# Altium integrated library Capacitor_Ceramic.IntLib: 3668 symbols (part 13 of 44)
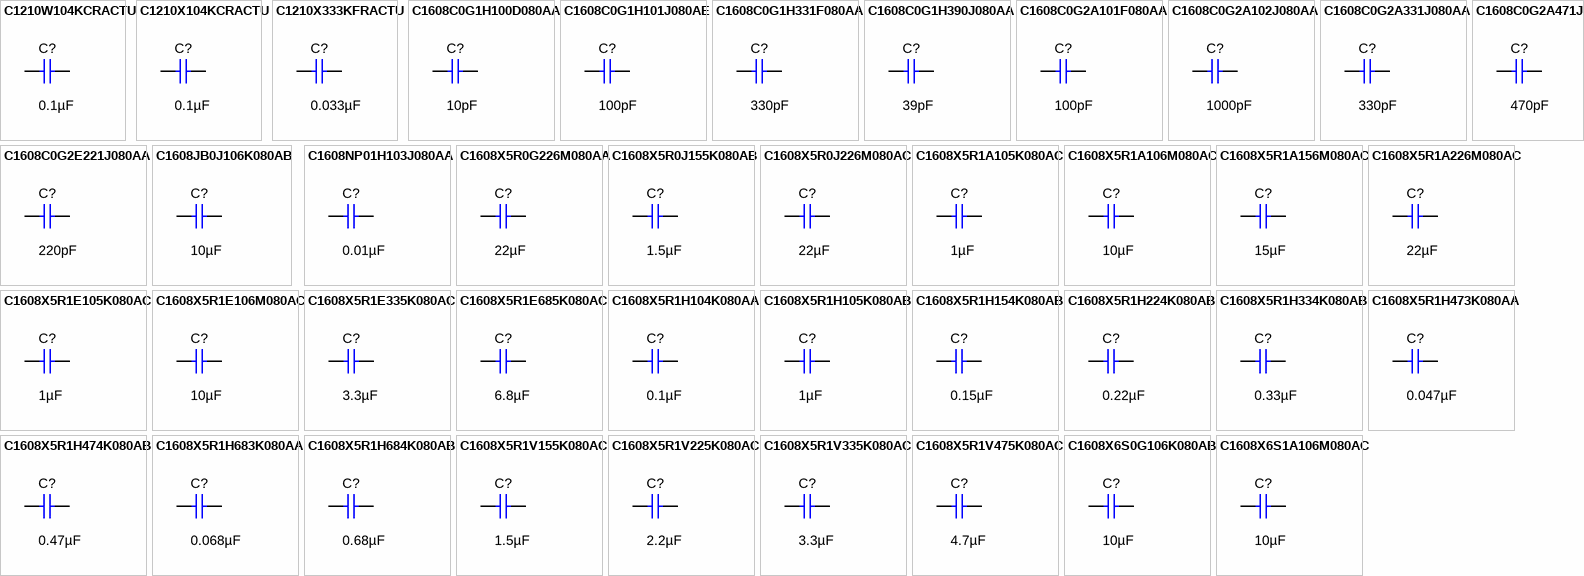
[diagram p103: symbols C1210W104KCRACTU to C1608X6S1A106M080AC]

## C1210X333KFRACTU
designator C?  ValueDisplayed: 0.033µF  (hidden comment: C1210X333KFRACTU)
CAP, CERM, 0.033 µF, 1500 V,+/- 10%, X7R, 1210; Manufacturer: Kemet; Polarized: N; CompType: Capacitor; Value: 0.033uF; U/M: EA; Cap_F: 0.000000033; Tolerance_%: 10; VDC_V: 1500; Value2: 1500V; TaMin_C: -55; TaMax_C: 125; Cap_Case: 1210; SizeArea_mm2: 8; SizeAreaWB_mm2: 14.7; SizeX_mm: 3.2; SizeY_mm: 2.5; SizeZ_mm: 2.8; AEC Category: Q200
signal-integrity model Cap
simulation model Cap
footprint 1210_280
pins: 1, 2

## C1608C0G1H100D080AA
designator C?  ValueDisplayed: 10pF  (hidden comment: C1608C0G1H100D080AA)
CAP, CERM, 10 pF, 50 V,+/- 5%, C0G/NP0, 0603; Manufacturer: TDK; Polarized: N; CompType: Capacitor; Value: 10pF; U/M: EA; Cap_F: 0.00000000001; Tolerance_%: 5; ESR_ohm: 0.3492; Value1: 0.3492 ohm; VDC_V: 50; Value2: 50V; TaMin_C: -55; TaMax_C: 125; Cap_Case: 0603; SizeArea_mm2: 1.28; SizeAreaWB_mm2: 4.68; SizeX_mm: 1.6; SizeY_mm: 0.8; SizeZ_mm: 1; AEC Category: Q200; Green_Lifecycle: NRND; Green_REACh: Passed
signal-integrity model Cap
simulation model Cap
footprint 0603
footprint 0603M
footprint 0603L
footprint 0603_HV
footprint 0603S
pins: 1, 2

## C1608C0G1H101J080AE
designator C?  ValueDisplayed: 100pF  (hidden comment: C1608C0G1H101J080AE)
CAP, CERM, 100 pF, 50 V,+/- 5%, C0G/NP0, 0603; Manufacturer: TDK; Polarized: N; CompType: Capacitor; Value: 100pF; U/M: EA; Cap_F: 0.0000000001; Tolerance_%: 5; VDC_V: 50; Value2: 50V; TaMin_C: -55; TaMax_C: 125; Cap_Case: 0603; SizeArea_mm2: 1.28; SizeAreaWB_mm2: 4.68; SizeX_mm: 1.6; SizeY_mm: 0.8; SizeZ_mm: 1; AEC Category: Q200; Green_Lifecycle: Active; Green_REACh: Passed
signal-integrity model Cap
simulation model Cap
footprint 0603
footprint 0603M
footprint 0603L
footprint 0603_HV
footprint 0603S
pins: 1, 2

## C1608C0G1H331F080AA
designator C?  ValueDisplayed: 330pF  (hidden comment: C1608C0G1H331F080AA)
CAP, CERM, 330 pF, 50 V,+/- 1%, C0G/NP0, 0603; Manufacturer: TDK; Polarized: N; CompType: Capacitor; Value: 330pF; U/M: EA; Cap_F: 0.00000000033; Tolerance_%: 1; VDC_V: 50; Value2: 50V; TaMin_C: -55; TaMax_C: 125; Cap_Case: 0603; SizeArea_mm2: 1.28; SizeAreaWB_mm2: 4.68; SizeX_mm: 1.6; SizeY_mm: 0.8; AEC Category: Q200; Green_Lifecycle: NRND; Green_REACh: Passed
signal-integrity model Cap
simulation model Cap
footprint 0603
footprint 0603M
footprint 0603L
footprint 0603_HV
footprint 0603S
pins: 1, 2

## C1608C0G1H390J080AA
designator C?  ValueDisplayed: 39pF  (hidden comment: C1608C0G1H390J080AA)
CAP, CERM, 39 pF, 50 V,+/- 5%, C0G/NP0, 0603; Manufacturer: TDK; Polarized: N; CompType: Capacitor; Value: 39pF; U/M: EA; Cap_F: 0.000000000039; Tolerance_%: 5; ESR_ohm: 0.2534; Value1: 0.2534 ohm; VDC_V: 50; Value2: 50V; TaMin_C: -55; TaMax_C: 125; Cap_Case: 0603; SizeArea_mm2: 1.28; SizeAreaWB_mm2: 4.68; SizeX_mm: 1.6; SizeY_mm: 0.8; SizeZ_mm: 1; AEC Category: Q200; Green_Lifecycle: NRND; Green_REACh: Passed
signal-integrity model Cap
simulation model Cap
footprint 0603
footprint 0603M
footprint 0603L
footprint 0603_HV
footprint 0603S
pins: 1, 2

## C1608C0G2A101F080AA
designator C?  ValueDisplayed: 100pF  (hidden comment: C1608C0G2A101F080AA)
CAP, CERM, 100 pF, 100 V,+/- 1%, C0G/NP0, 0603; Manufacturer: TDK; Polarized: N; CompType: Capacitor; Value: 100pF; U/M: EA; Cap_F: 0.0000000001; Tolerance_%: 1; VDC_V: 100; Value2: 100V; TaMin_C: -55; TaMax_C: 125; Cap_Case: 0603; SizeArea_mm2: 1.28; SizeAreaWB_mm2: 4.68; SizeX_mm: 1.6; SizeY_mm: 0.8; AEC Category: Q200; Green_Lifecycle: NRND; Green_REACh: Passed
signal-integrity model Cap
simulation model Cap
footprint 0603
footprint 0603M
footprint 0603L
footprint 0603_HV
footprint 0603S
pins: 1, 2

## C1608C0G2A102J080AA
designator C?  ValueDisplayed: 1000pF  (hidden comment: C1608C0G2A102J080AA)
CAP, CERM, 1000 pF, 100 V,+/- 5%, C0G/NP0, 0603; Manufacturer: TDK; Polarized: N; CompType: Capacitor; Value: 1000pF; U/M: EA; Cap_F: 0.000000001; Tolerance_%: 5; ESR_ohm: 0.0589; Value1: 0.0589 ohm; VDC_V: 100; Value2: 100V; TaMin_C: -55; TaMax_C: 125; Cap_Case: 0603; SizeArea_mm2: 1.28; SizeAreaWB_mm2: 4.68; SizeX_mm: 1.6; SizeY_mm: 0.8; SizeZ_mm: 1; AEC Category: Q200; Green_Lifecycle: Active; Green_REACh: Passed
signal-integrity model Cap
simulation model Cap
footprint 0603
footprint 0603M
footprint 0603L
footprint 0603_HV
footprint 0603S
pins: 1, 2

## C1608C0G2A331J080AA
designator C?  ValueDisplayed: 330pF  (hidden comment: C1608C0G2A331J080AA)
CAP, CERM, 330 pF, 100 V,+/- 5%, C0G/NP0, 0603; Manufacturer: TDK; Polarized: N; CompType: Capacitor; Value: 330pF; U/M: EA; Cap_F: 0.00000000033; Tolerance_%: 5; ESR_ohm: 0.1269; Value1: 0.1269 ohm; VDC_V: 100; Value2: 100V; TaMin_C: -55; TaMax_C: 125; Cap_Case: 0603; SizeArea_mm2: 1.28; SizeAreaWB_mm2: 4.68; SizeX_mm: 1.6; SizeY_mm: 0.8; SizeZ_mm: 1; AEC Category: Q200; Green_Lifecycle: Active; Green_REACh: Passed
signal-integrity model Cap
simulation model Cap
footprint 0603
footprint 0603M
footprint 0603L
footprint 0603_HV
footprint 0603S
pins: 1, 2

## C1608C0G2A471J
designator C?  ValueDisplayed: 470pF  (hidden comment: C1608C0G2A471J)
CAP, CERM, 470 pF, 100 V,+/- 5%, C0G/NP0, 0603; Manufacturer: TDK; Polarized: N; CompType: Capacitor; Value: 470pF; U/M: EA; Cap_F: 0.00000000047; Tolerance_%: 5; ESR_ohm: 0.0714; Value1: 0.0714 ohm; VDC_V: 100; Value2: 100V; TaMin_C: -55; TaMax_C: 125; Cap_Case: 0603; SizeArea_mm2: 1.28; SizeAreaWB_mm2: 4.68; SizeX_mm: 1.6; SizeY_mm: 0.8; SizeZ_mm: 1; AEC Category: Q200; Green_Lifecycle: Not Set; Green_REACh: Incomplete
signal-integrity model Cap
simulation model Cap
footprint 0603
footprint 0603M
footprint 0603L
footprint 0603_HV
footprint 0603S
pins: 1, 2

## C1608C0G2E221J080AA
designator C?  ValueDisplayed: 220pF  (hidden comment: C1608C0G2E221J080AA)
CAP, CERM, 220 pF, 250 V,+/- 5%, C0G/NP0, 0603; Manufacturer: TDK; Polarized: N; CompType: Capacitor; Value: 220pF; U/M: EA; Cap_F: 0.00000000022; Tolerance_%: 5; VDC_V: 250; Value2: 250V; TaMin_C: -55; TaMax_C: 125; Cap_Case: 0603; SizeArea_mm2: 1.28; SizeAreaWB_mm2: 4.68; SizeX_mm: 1.6; SizeY_mm: 0.8; SizeZ_mm: 1; AEC Category: Q200
signal-integrity model Cap
simulation model Cap
footprint 0603
footprint 0603M
footprint 0603L
footprint 0603_HV
footprint 0603S
pins: 1, 2

## C1608JB0J106K080AB
designator C?  ValueDisplayed: 10µF  (hidden comment: C1608JB0J106K080AB)
CAP, CERM, 10 µF, 6.3 V,+/- 10%, JB, 0603; Manufacturer: TDK; Polarized: N; CompType: Capacitor; Value: 10uF; U/M: EA; Cap_F: 0.00001; Tolerance_%: 10; VDC_V: 6.3; Value2: 6.3V; TaMin_C: -25; TaMax_C: 85; Cap_Case: 0603; SizeArea_mm2: 1.28; SizeAreaWB_mm2: 4.68; SizeX_mm: 1.6; SizeY_mm: 0.8; SizeZ_mm: 1; AEC Category: Q200
signal-integrity model Cap
simulation model Cap
footprint 0603
footprint 0603M
footprint 0603L
footprint 0603_HV
footprint 0603S
pins: 1, 2

## C1608NP01H103J080AA
designator C?  ValueDisplayed: 0.01µF  (hidden comment: C1608NP01H103J080AA)
CAP, CERM, 0.01 µF, 50 V,+/- 5%, C0G/NP0, 0603; Manufacturer: TDK; Polarized: N; CompType: Capacitor; Value: 0.01uF; U/M: EA; Cap_F: 0.00000001; Tolerance_%: 5; VDC_V: 50; Value2: 50V; TaMin_C: -55; TaMax_C: 150; Cap_Case: 0603; SizeArea_mm2: 1.28; SizeAreaWB_mm2: 4.68; SizeX_mm: 1.6; SizeY_mm: 0.8; SizeZ_mm: 1; AEC Category: Q200; Green_Lifecycle: Not Set; Green_REACh: Incomplete
signal-integrity model Cap
simulation model Cap
footprint 0603
footprint 0603M
footprint 0603L
footprint 0603_HV
footprint 0603S
pins: 1, 2

## C1608X5R0G226M080AA
designator C?  ValueDisplayed: 22µF  (hidden comment: C1608X5R0G226M080AA)
CAP, CERM, 22 µF, 4 V,+/- 20%, X5R, 0603; Manufacturer: TDK; Polarized: N; CompType: Capacitor; Value: 22uF; U/M: EA; Cap_F: 0.000022; Tolerance_%: 20; VDC_V: 4; Value2: 4V; TaMin_C: -55; TaMax_C: 85; Cap_Case: 0603; SizeArea_mm2: 1.28; SizeAreaWB_mm2: 4.68; SizeX_mm: 1.6; SizeY_mm: 0.8; SizeZ_mm: 1; AEC Category: Q200; Green_Lifecycle: Active; Green_REACh: Passed
signal-integrity model Cap
simulation model Cap
footprint 0603
footprint 0603M
footprint 0603L
footprint 0603_HV
footprint 0603S
pins: 1, 2

## C1608X5R0J155K080AB
designator C?  ValueDisplayed: 1.5µF  (hidden comment: C1608X5R0J155K080AB)
CAP, CERM, 1.5 µF, 6.3 V,+/- 10%, X5R, 0603; Manufacturer: TDK; Polarized: N; CompType: Capacitor; Value: 1.5uF; U/M: EA; Cap_F: 0.0000015; Tolerance_%: 10; VDC_V: 6.3; Value2: 6.3V; TaMin_C: -55; TaMax_C: 85; Cap_Case: 0603; SizeArea_mm2: 1.28; SizeAreaWB_mm2: 4.68; SizeX_mm: 1.6; SizeY_mm: 0.8; SizeZ_mm: 1; AEC Category: Q200
signal-integrity model Cap
simulation model Cap
footprint 0603
footprint 0603M
footprint 0603L
footprint 0603_HV
footprint 0603S
pins: 1, 2

## C1608X5R0J226M080AC
designator C?  ValueDisplayed: 22µF  (hidden comment: C1608X5R0J226M080AC)
CAP, CERM, 22 µF, 6.3 V,+/- 20%, X5R, 0603; Manufacturer: TDK; Polarized: N; CompType: Capacitor; Value: 22uF; U/M: EA; Cap_F: 0.000022; Tolerance_%: 20; VDC_V: 6.3; Value2: 6.3V; TaMin_C: -55; TaMax_C: 85; Cap_Case: 0603; SizeArea_mm2: 1.28; SizeAreaWB_mm2: 4.68; SizeX_mm: 1.6; SizeY_mm: 0.8; SizeZ_mm: 1; AEC Category: Q200; Green_Lifecycle: Active; Green_REACh: Passed
signal-integrity model Cap
simulation model Cap
footprint 0603
footprint 0603M
footprint 0603L
footprint 0603_HV
footprint 0603S
pins: 1, 2

## C1608X5R1A105K080AC
designator C?  ValueDisplayed: 1µF  (hidden comment: C1608X5R1A105K080AC)
CAP, CERM, 1 µF, 10 V,+/- 10%, X5R, 0603; Manufacturer: TDK; Polarized: N; CompType: Capacitor; Value: 1uF; U/M: EA; Cap_F: 0.000001; Tolerance_%: 10; Value2: 10V; TaMin_C: -55; TaMax_C: 85; Cap_Case: 0603; SizeArea_mm2: 1.28; SizeAreaWB_mm2: 4.68; SizeX_mm: 1.6; SizeY_mm: 0.8; SizeZ_mm: 1; AEC Category: Q200; Green_Lifecycle: NRND; Green_REACh: Passed
signal-integrity model Cap
simulation model Cap
footprint 0603
footprint 0603M
footprint 0603L
footprint 0603_HV
footprint 0603S
pins: 1, 2

## C1608X5R1A106M080AC
designator C?  ValueDisplayed: 10µF  (hidden comment: C1608X5R1A106M080AC)
CAP, CERM, 10 µF, 10 V,+/- 20%, X5R, 0603; Manufacturer: TDK; Polarized: N; CompType: Capacitor; Value: 10uF; U/M: EA; Cap_F: 0.00001; Tolerance_%: 20; ESR_ohm: 0.0078; Value1: 0.0078 ohm; VDC_V: 10; Value2: 10V; IRMS_A: 1.85; TaMin_C: -55; TaMax_C: 85; Cap_Case: 0603; SizeArea_mm2: 1.28; SizeAreaWB_mm2: 4.68; SizeX_mm: 1.6; SizeY_mm: 0.8; SizeZ_mm: 1; AEC Category: Q200; Green_Lifecycle: Active; Green_REACh: Passed
signal-integrity model Cap
simulation model Cap
footprint 0603
footprint 0603M
footprint 0603L
footprint 0603_HV
footprint 0603S
pins: 1, 2

## C1608X5R1A156M080AC
designator C?  ValueDisplayed: 15µF  (hidden comment: C1608X5R1A156M080AC)
CAP, CERM, 15 µF, 10 V,+/- 20%, X5R, 0603; Manufacturer: TDK; Polarized: N; CompType: Capacitor; Value: 15uF; U/M: EA; Cap_F: 0.000015; Tolerance_%: 20; ESR_ohm: 0.006531; Value1: 0.006531 ohm; VDC_V: 10; Value2: 10V; IRMS_A: 2.03438; TaMin_C: -55; TaMax_C: 85; Cap_Case: 0603; SizeArea_mm2: 1.28; SizeAreaWB_mm2: 4.68; SizeX_mm: 1.6; SizeY_mm: 0.8; SizeZ_mm: 1; AEC Category: Q200
signal-integrity model Cap
simulation model Cap
footprint 0603
footprint 0603M
footprint 0603L
footprint 0603_HV
footprint 0603S
pins: 1, 2

## C1608X5R1A226M080AC
designator C?  ValueDisplayed: 22µF  (hidden comment: C1608X5R1A226M080AC)
CAP, CERM, 22 µF, 10 V,+/- 20%, X5R, 0603; Manufacturer: TDK; Polarized: N; CompType: Capacitor; Value: 22uF; U/M: EA; Cap_F: 0.000022; Tolerance_%: 20; ESR_ohm: 0.00371; Value1: 0.00371 ohm; VDC_V: 10; Value2: 10V; IRMS_A: 2.69936; TaMin_C: -55; TaMax_C: 85; Cap_Case: 0603; SizeArea_mm2: 1.28; SizeAreaWB_mm2: 4.68; SizeX_mm: 1.6; SizeY_mm: 0.8; SizeZ_mm: 1; AEC Category: Q200; Green_Lifecycle: Active; Green_REACh: Passed
signal-integrity model Cap
simulation model Cap
footprint 0603
footprint 0603M
footprint 0603L
footprint 0603_HV
footprint 0603S
pins: 1, 2

## C1608X5R1E105K080AC
designator C?  ValueDisplayed: 1µF  (hidden comment: C1608X5R1E105K080AC)
CAP, CERM, 1 µF, 25 V,+/- 10%, X5R, 0603; Manufacturer: TDK; Polarized: N; CompType: Capacitor; Value: 1uF; U/M: EA; Cap_F: 0.000001; Tolerance_%: 10; VDC_V: 25; Value2: 25V; TaMin_C: -55; TaMax_C: 85; Cap_Case: 0603; SizeArea_mm2: 1.28; SizeAreaWB_mm2: 4.68; SizeX_mm: 1.6; SizeY_mm: 0.8; SizeZ_mm: 1; AEC Category: Q200; Green_Lifecycle: Active; Green_REACh: Passed
signal-integrity model Cap
simulation model Cap
footprint 0603
footprint 0603M
footprint 0603L
footprint 0603_HV
footprint 0603S
pins: 1, 2

## C1608X5R1E106M080AC
designator C?  ValueDisplayed: 10µF  (hidden comment: C1608X5R1E106M080AC)
CAP, CERM, 10 µF, 25 V,+/- 20%, X5R, 0603; Manufacturer: TDK; Polarized: N; CompType: Capacitor; Value: 10uF; U/M: EA; Cap_F: 0.00001; Tolerance_%: 20; ESR_ohm: 0.004639; Value1: 0.004639 ohm; VDC_V: 25; Value2: 25V; IRMS_A: 2.41407; TaMin_C: -55; TaMax_C: 85; Cap_Case: 0603; SizeArea_mm2: 1.28; SizeAreaWB_mm2: 4.68; SizeX_mm: 1.6; SizeY_mm: 0.8; SizeZ_mm: 1; AEC Category: Q200; Green_Lifecycle: Active; Green_REACh: Passed
signal-integrity model Cap
simulation model Cap
footprint 0603
footprint 0603M
footprint 0603L
footprint 0603_HV
footprint 0603S
pins: 1, 2

## C1608X5R1E335K080AC
designator C?  ValueDisplayed: 3.3µF  (hidden comment: C1608X5R1E335K080AC)
CAP, CERM, 3.3 µF, 25 V,+/- 10%, X5R, 0603; Manufacturer: TDK; Polarized: N; CompType: Capacitor; Value: 3.3uF; U/M: EA; Cap_F: 0.0000033; Tolerance_%: 10; VDC_V: 25; Value2: 25V; TaMin_C: -55; TaMax_C: 85; Cap_Case: 0603; SizeArea_mm2: 1.28; SizeAreaWB_mm2: 4.68; SizeX_mm: 1.6; SizeY_mm: 0.8; SizeZ_mm: 1; AEC Category: Q200; Green_Lifecycle: Active; Green_REACh: Passed
signal-integrity model Cap
simulation model Cap
footprint 0603
footprint 0603M
footprint 0603L
footprint 0603_HV
footprint 0603S
pins: 1, 2

## C1608X5R1E685K080AC
designator C?  ValueDisplayed: 6.8µF  (hidden comment: C1608X5R1E685K080AC)
CAP, CERM, 6.8 µF, 25 V,+/- 10%, X5R, 0603; Manufacturer: TDK; Polarized: N; CompType: Capacitor; Value: 6.8uF; U/M: EA; Cap_F: 0.0000068; Tolerance_%: 10; ESR_ohm: 0.004211; Value1: 0.004211 ohm; VDC_V: 25; Value2: 25V; IRMS_A: 2.534067; TaMin_C: -55; TaMax_C: 85; Cap_Case: 0603; SizeArea_mm2: 1.28; SizeAreaWB_mm2: 4.68; SizeX_mm: 1.6; SizeY_mm: 0.8; SizeZ_mm: 1; AEC Category: Q200
signal-integrity model Cap
simulation model Cap
footprint 0603
footprint 0603M
footprint 0603L
footprint 0603_HV
footprint 0603S
pins: 1, 2

## C1608X5R1H104K080AA
designator C?  ValueDisplayed: 0.1µF  (hidden comment: C1608X5R1H104K080AA)
CAP, CERM, 0.1 µF, 50 V,+/- 10%, X5R, 0603; Manufacturer: TDK; Polarized: N; CompType: Capacitor; Value: 0.1uF; U/M: EA; Cap_F: 0.0000001; Tolerance_%: 10; ESR_ohm: 0.0296; Value1: 0.0296 ohm; VDC_V: 50; Value2: 50V; IRMS_A: 0.97199; TaMin_C: -55; TaMax_C: 85; Cap_Case: 0603; SizeArea_mm2: 1.28; SizeAreaWB_mm2: 4.68; SizeX_mm: 1.6; SizeY_mm: 0.8; SizeZ_mm: 1; AEC Category: Q200; Green_Lifecycle: NRND; Green_REACh: Passed
signal-integrity model Cap
simulation model Cap
footprint 0603
footprint 0603M
footprint 0603L
footprint 0603_HV
footprint 0603S
pins: 1, 2

## C1608X5R1H105K080AB
designator C?  ValueDisplayed: 1µF  (hidden comment: C1608X5R1H105K080AB)
CAP, CERM, 1 µF, 50 V,+/- 10%, X5R, 0603; Manufacturer: TDK; Polarized: N; CompType: Capacitor; Value: 1uF; U/M: EA; Cap_F: 0.000001; Tolerance_%: 10; ESR_ohm: 0.005522; Value1: 0.005522 ohm; VDC_V: 50; Value2: 50V; IRMS_A: 2.21617; TaMin_C: -55; TaMax_C: 85; Cap_Case: 0603; SizeArea_mm2: 1.28; SizeAreaWB_mm2: 4.68; SizeX_mm: 1.6; SizeY_mm: 0.8; SizeZ_mm: 1; AEC Category: Q200; Green_Lifecycle: Active; Green_REACh: Passed
signal-integrity model Cap
simulation model Cap
footprint 0603
footprint 0603M
footprint 0603L
footprint 0603_HV
footprint 0603S
pins: 1, 2

## C1608X5R1H154K080AB
designator C?  ValueDisplayed: 0.15µF  (hidden comment: C1608X5R1H154K080AB)
CAP, CERM, 0.15 µF, 50 V,+/- 10%, X5R, 0603; Manufacturer: TDK; Polarized: N; CompType: Capacitor; Value: 0.15uF; U/M: EA; Cap_F: 0.00000015; Tolerance_%: 10; ESR_ohm: 0.028863; Value1: 0.028863 ohm; VDC_V: 50; Value2: 50V; IRMS_A: 0.978809; TaMin_C: -55; TaMax_C: 85; Cap_Case: 0603; SizeArea_mm2: 1.28; SizeAreaWB_mm2: 4.68; SizeX_mm: 1.6; SizeY_mm: 0.8; SizeZ_mm: 1; AEC Category: Q200
signal-integrity model Cap
simulation model Cap
footprint 0603
footprint 0603M
footprint 0603L
footprint 0603_HV
footprint 0603S
pins: 1, 2

## C1608X5R1H224K080AB
designator C?  ValueDisplayed: 0.22µF  (hidden comment: C1608X5R1H224K080AB)
CAP, CERM, 0.22 µF, 50 V,+/- 10%, X5R, 0603; Manufacturer: TDK; Polarized: N; CompType: Capacitor; Value: 0.22uF; U/M: EA; Cap_F: 0.00000022; Tolerance_%: 10; ESR_ohm: 0.021699; Value1: 0.021699 ohm; VDC_V: 50; Value2: 50V; IRMS_A: 1.12496; TaMin_C: -55; TaMax_C: 85; Cap_Case: 0603; SizeArea_mm2: 1.28; SizeAreaWB_mm2: 4.68; SizeX_mm: 1.6; SizeY_mm: 0.8; SizeZ_mm: 1; AEC Category: Q200
signal-integrity model Cap
simulation model Cap
footprint 0603
footprint 0603M
footprint 0603L
footprint 0603_HV
footprint 0603S
pins: 1, 2

## C1608X5R1H334K080AB
designator C?  ValueDisplayed: 0.33µF  (hidden comment: C1608X5R1H334K080AB)
CAP, CERM, 0.33 µF, 50 V,+/- 10%, X5R, 0603; Manufacturer: TDK; Polarized: N; CompType: Capacitor; Value: 0.33uF; U/M: EA; Cap_F: 0.00000033; Tolerance_%: 10; ESR_ohm: 0.016574; Value1: 0.016574 ohm; VDC_V: 50; Value2: 50V; IRMS_A: 1.28367; TaMin_C: -55; TaMax_C: 85; Cap_Case: 0603; SizeArea_mm2: 1.28; SizeAreaWB_mm2: 4.68; SizeX_mm: 1.6; SizeY_mm: 0.8; SizeZ_mm: 1; AEC Category: Q200
signal-integrity model Cap
simulation model Cap
footprint 0603
footprint 0603M
footprint 0603L
footprint 0603_HV
footprint 0603S
pins: 1, 2

## C1608X5R1H473K080AA
designator C?  ValueDisplayed: 0.047µF  (hidden comment: C1608X5R1H473K080AA)
CAP, CERM, 0.047 µF, 50 V,+/- 10%, X5R, 0603; Manufacturer: TDK; Polarized: N; CompType: Capacitor; Value: 0.047uF; U/M: EA; Cap_F: 0.000000047; Tolerance_%: 10; ESR_ohm: 0.049007; Value1: 0.049007 ohm; VDC_V: 50; Value2: 50V; IRMS_A: 0.767528; TaMin_C: -55; TaMax_C: 85; Cap_Case: 0603; SizeArea_mm2: 1.28; SizeAreaWB_mm2: 4.68; SizeX_mm: 1.6; SizeY_mm: 0.8; SizeZ_mm: 1; AEC Category: Q200; Green_Lifecycle: NRND; Green_REACh: Passed
signal-integrity model Cap
simulation model Cap
footprint 0603
footprint 0603M
footprint 0603L
footprint 0603_HV
footprint 0603S
pins: 1, 2

## C1608X5R1H474K080AB
designator C?  ValueDisplayed: 0.47µF  (hidden comment: C1608X5R1H474K080AB)
CAP, CERM, 0.47 µF, 50 V,+/- 10%, X5R, 0603; Manufacturer: TDK; Polarized: N; CompType: Capacitor; Value: 0.47uF; U/M: EA; Cap_F: 0.00000047; Tolerance_%: 10; ESR_ohm: 0.010974; Value1: 0.010974 ohm; VDC_V: 50; Value2: 50V; IRMS_A: 1.57483; TaMin_C: -55; TaMax_C: 85; Cap_Case: 0603; SizeArea_mm2: 1.28; SizeAreaWB_mm2: 4.68; SizeX_mm: 1.6; SizeY_mm: 0.8; SizeZ_mm: 1; AEC Category: Q200
signal-integrity model Cap
simulation model Cap
footprint 0603
footprint 0603M
footprint 0603L
footprint 0603_HV
footprint 0603S
pins: 1, 2

## C1608X5R1H683K080AA
designator C?  ValueDisplayed: 0.068µF  (hidden comment: C1608X5R1H683K080AA)
CAP, CERM, 0.068 µF, 50 V,+/- 10%, X5R, 0603; Manufacturer: TDK; Polarized: N; CompType: Capacitor; Value: 0.068uF; U/M: EA; Cap_F: 0.000000068; Tolerance_%: 10; ESR_ohm: 0.035979; Value1: 0.035979 ohm; VDC_V: 50; Value2: 50V; IRMS_A: 0.886483; TaMin_C: -55; TaMax_C: 85; Cap_Case: 0603; SizeArea_mm2: 1.28; SizeAreaWB_mm2: 4.68; SizeX_mm: 1.6; SizeY_mm: 0.8; SizeZ_mm: 1; AEC Category: Q200; Green_Lifecycle: NRND; Green_REACh: Passed
signal-integrity model Cap
simulation model Cap
footprint 0603
footprint 0603M
footprint 0603L
footprint 0603_HV
footprint 0603S
pins: 1, 2

## C1608X5R1H684K080AB
designator C?  ValueDisplayed: 0.68µF  (hidden comment: C1608X5R1H684K080AB)
CAP, CERM, 0.68 µF, 50 V,+/- 10%, X5R, 0603; Manufacturer: TDK; Polarized: N; CompType: Capacitor; Value: 0.68uF; U/M: EA; Cap_F: 0.00000068; Tolerance_%: 10; ESR_ohm: 0.007125; Value1: 0.007125 ohm; VDC_V: 50; Value2: 50V; IRMS_A: 1.9522; TaMin_C: -55; TaMax_C: 85; Cap_Case: 0603; SizeArea_mm2: 1.28; SizeAreaWB_mm2: 4.68; SizeX_mm: 1.6; SizeY_mm: 0.8; SizeZ_mm: 1; AEC Category: Q200
signal-integrity model Cap
simulation model Cap
footprint 0603
footprint 0603M
footprint 0603L
footprint 0603_HV
footprint 0603S
pins: 1, 2

## C1608X5R1V155K080AC
designator C?  ValueDisplayed: 1.5µF  (hidden comment: C1608X5R1V155K080AC)
CAP, CERM, 1.5 µF, 35 V,+/- 10%, X5R, 0603; Manufacturer: TDK; Polarized: N; CompType: Capacitor; Value: 1.5uF; U/M: EA; Cap_F: 0.0000015; Tolerance_%: 10; ESR_ohm: 0.009039; Value1: 0.009039 ohm; VDC_V: 35; Value2: 35V; IRMS_A: 1.73141; TaMin_C: -55; TaMax_C: 85; Cap_Case: 0603; SizeArea_mm2: 1.28; SizeAreaWB_mm2: 4.68; SizeX_mm: 1.6; SizeY_mm: 0.8; SizeZ_mm: 1; AEC Category: Q200
signal-integrity model Cap
simulation model Cap
footprint 0603
footprint 0603M
footprint 0603L
footprint 0603_HV
footprint 0603S
pins: 1, 2

## C1608X5R1V225K080AC
designator C?  ValueDisplayed: 2.2µF  (hidden comment: C1608X5R1V225K080AC)
CAP, CERM, 2.2 µF, 35 V,+/- 10%, X5R, 0603; Manufacturer: TDK; Polarized: N; CompType: Capacitor; Value: 2.2uF; U/M: EA; Cap_F: 0.0000022; Tolerance_%: 10; ESR_ohm: 0.007674; Value1: 0.007674 ohm; VDC_V: 35; Value2: 35V; IRMS_A: 1.87823; TaMin_C: -55; TaMax_C: 85; Cap_Case: 0603; SizeArea_mm2: 1.28; SizeAreaWB_mm2: 4.68; SizeX_mm: 1.6; SizeY_mm: 0.8; SizeZ_mm: 1; AEC Category: Q200; Green_Lifecycle: Active; Green_REACh: Passed
signal-integrity model Cap
simulation model Cap
footprint 0603
footprint 0603M
footprint 0603L
footprint 0603_HV
footprint 0603S
pins: 1, 2

## C1608X5R1V335K080AC
designator C?  ValueDisplayed: 3.3µF  (hidden comment: C1608X5R1V335K080AC)
CAP, CERM, 3.3 µF, 35 V,+/- 10%, X5R, 0603; Manufacturer: TDK; Polarized: N; CompType: Capacitor; Value: 3.3uF; U/M: EA; Cap_F: 0.0000033; Tolerance_%: 10; ESR_ohm: 0.004796; Value1: 0.004796 ohm; VDC_V: 35; Value2: 35V; IRMS_A: 2.37519; TaMin_C: -55; TaMax_C: 85; Cap_Case: 0603; SizeArea_mm2: 1.28; SizeAreaWB_mm2: 4.68; SizeX_mm: 1.6; SizeY_mm: 0.8; SizeZ_mm: 1; AEC Category: Q200
signal-integrity model Cap
simulation model Cap
footprint 0603
footprint 0603M
footprint 0603L
footprint 0603_HV
footprint 0603S
pins: 1, 2

## C1608X5R1V475K080AC
designator C?  ValueDisplayed: 4.7µF  (hidden comment: C1608X5R1V475K080AC)
CAP, CERM, 4.7 µF, 35 V,+/- 10%, X5R, 0603; Manufacturer: TDK; Polarized: N; CompType: Capacitor; Value: 4.7uF; U/M: EA; Cap_F: 0.0000047; Tolerance_%: 10; ESR_ohm: 0.003728; Value1: 0.003728 ohm; VDC_V: 35; Value2: 35V; IRMS_A: 2.69359; TaMin_C: -55; TaMax_C: 85; Cap_Case: 0603; SizeArea_mm2: 1.28; SizeAreaWB_mm2: 4.68; SizeX_mm: 1.6; SizeY_mm: 0.8; SizeZ_mm: 1; AEC Category: Q200
signal-integrity model Cap
simulation model Cap
footprint 0603
footprint 0603M
footprint 0603L
footprint 0603_HV
footprint 0603S
pins: 1, 2

## C1608X6S0G106K080AB
designator C?  ValueDisplayed: 10µF  (hidden comment: C1608X6S0G106K080AB)
CAP, CERM, 10 µF, 4 V,+/- 10%, X6S, 0603; Manufacturer: TDK; Polarized: N; CompType: Capacitor; Value: 10uF; U/M: EA; Cap_F: 0.00001; Tolerance_%: 10; VDC_V: 4; Value2: 4V; TaMin_C: -55; TaMax_C: 105; Cap_Case: 0603; SizeArea_mm2: 1.28; SizeAreaWB_mm2: 4.68; SizeX_mm: 1.6; SizeY_mm: 0.8; SizeZ_mm: 1; AEC Category: Q200
signal-integrity model Cap
simulation model Cap
footprint 0603
footprint 0603M
footprint 0603L
footprint 0603_HV
footprint 0603S
pins: 1, 2

## C1608X6S1A106M080AC
designator C?  ValueDisplayed: 10µF  (hidden comment: C1608X6S1A106M080AC)
CAP, CERM, 10 µF, 10 V,+/- 10%, X6S, 0603; Manufacturer: TDK; Polarized: N; CompType: Capacitor; Value: 10uF; U/M: EA; Cap_F: 0.00001; Tolerance_%: 10; ESR_ohm: 0.004639; Value1: 0.004639 ohm; Value2: 10V; IRMS_A: 2.41407; TaMin_C: -55; TaMax_C: 105; Cap_Case: 0603; SizeArea_mm2: 1.28; SizeAreaWB_mm2: 4.68; SizeX_mm: 1.6; SizeY_mm: 0.8; SizeZ_mm: 1; AEC Category: Q200
signal-integrity model Cap
simulation model Cap
footprint 0603
footprint 0603M
footprint 0603L
footprint 0603_HV
footprint 0603S
pins: 1, 2

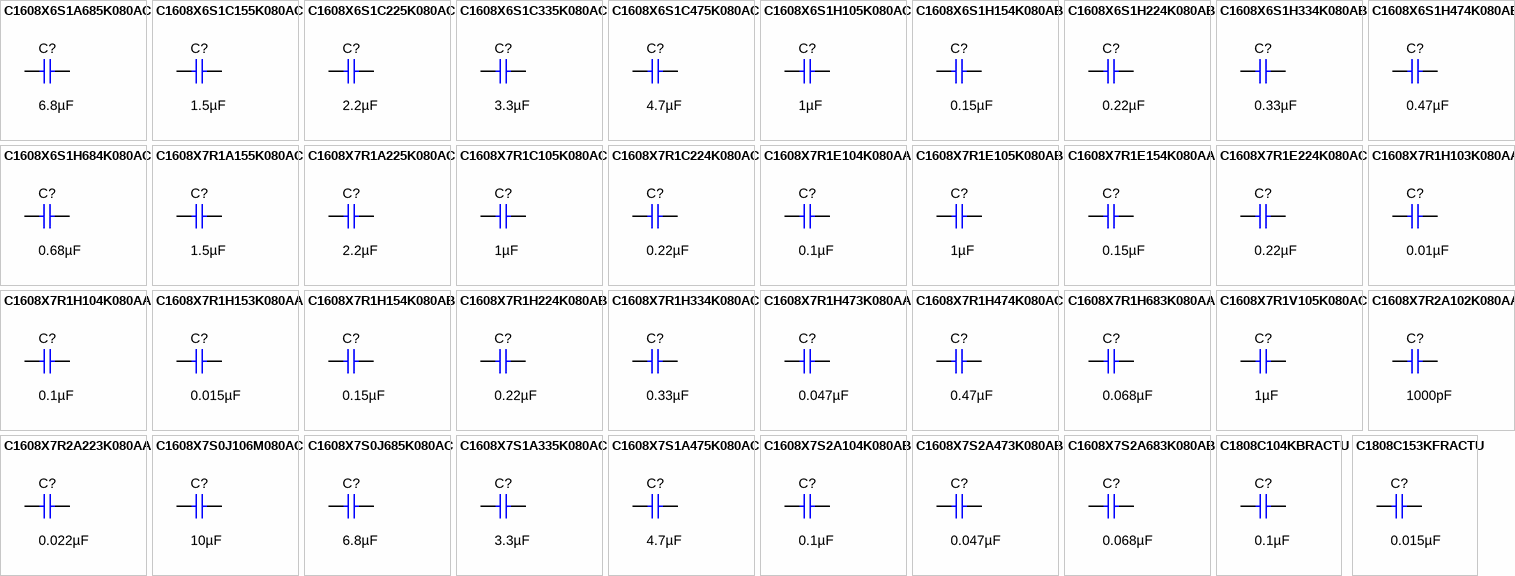
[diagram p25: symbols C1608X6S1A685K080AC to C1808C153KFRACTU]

## C1608X6S1A685K080AC
designator C?  ValueDisplayed: 6.8µF  (hidden comment: C1608X6S1A685K080AC)
CAP, CERM, 6.8 µF, 10 V,+/- 10%, X6S, 0603; Manufacturer: TDK; Polarized: N; CompType: Capacitor; Value: 6.8uF; U/M: EA; Cap_F: 0.0000068; Tolerance_%: 10; ESR_ohm: 0.004211; Value1: 0.004211 ohm; Value2: 10V; IRMS_A: 2.534067; TaMin_C: -55; TaMax_C: 105; Cap_Case: 0603; SizeArea_mm2: 1.28; SizeAreaWB_mm2: 4.68; SizeX_mm: 1.6; SizeY_mm: 0.8; SizeZ_mm: 1; AEC Category: Q200
signal-integrity model Cap
simulation model Cap
footprint 0603
footprint 0603M
footprint 0603L
footprint 0603_HV
footprint 0603S
pins: 1, 2

## C1608X6S1C155K080AC
designator C?  ValueDisplayed: 1.5µF  (hidden comment: C1608X6S1C155K080AC)
CAP, CERM, 1.5 µF, 16 V,+/- 10%, X6S, 0603; Manufacturer: TDK; Polarized: N; CompType: Capacitor; Value: 1.5uF; U/M: EA; Cap_F: 0.0000015; Tolerance_%: 10; ESR_ohm: 0.009039; Value1: 0.009039 ohm; VDC_V: 16; Value2: 16V; IRMS_A: 1.73141; TaMin_C: -55; TaMax_C: 105; Cap_Case: 0603; SizeArea_mm2: 1.28; SizeAreaWB_mm2: 4.68; SizeX_mm: 1.6; SizeY_mm: 0.8; SizeZ_mm: 1; AEC Category: Q200
signal-integrity model Cap
simulation model Cap
footprint 0603
footprint 0603M
footprint 0603L
footprint 0603_HV
footprint 0603S
pins: 1, 2

## C1608X6S1C225K080AC
designator C?  ValueDisplayed: 2.2µF  (hidden comment: C1608X6S1C225K080AC)
CAP, CERM, 2.2 µF, 16 V,+/- 10%, X6S, 0603; Manufacturer: TDK; Polarized: N; CompType: Capacitor; Value: 2.2uF; U/M: EA; Cap_F: 0.0000022; Tolerance_%: 10; ESR_ohm: 0.007674; Value1: 0.007674 ohm; VDC_V: 16; Value2: 16V; IRMS_A: 1.87823; TaMin_C: -55; TaMax_C: 105; Cap_Case: 0603; SizeArea_mm2: 1.28; SizeAreaWB_mm2: 4.68; SizeX_mm: 1.6; SizeY_mm: 0.8; SizeZ_mm: 1; AEC Category: Q200
signal-integrity model Cap
simulation model Cap
footprint 0603
footprint 0603M
footprint 0603L
footprint 0603_HV
footprint 0603S
pins: 1, 2

## C1608X6S1C335K080AC
designator C?  ValueDisplayed: 3.3µF  (hidden comment: C1608X6S1C335K080AC)
CAP, CERM, 3.3 µF, 16 V,+/- 10%, X6S, 0603; Manufacturer: TDK; Polarized: N; CompType: Capacitor; Value: 3.3uF; U/M: EA; Cap_F: 0.0000033; Tolerance_%: 10; ESR_ohm: 0.004796; Value1: 0.004796 ohm; VDC_V: 16; Value2: 16V; IRMS_A: 2.37519; TaMin_C: -55; TaMax_C: 105; Cap_Case: 0603; SizeArea_mm2: 1.28; SizeAreaWB_mm2: 4.68; SizeX_mm: 1.6; SizeY_mm: 0.8; SizeZ_mm: 1; AEC Category: Q200
signal-integrity model Cap
simulation model Cap
footprint 0603
footprint 0603M
footprint 0603L
footprint 0603_HV
footprint 0603S
pins: 1, 2

## C1608X6S1C475K080AC
designator C?  ValueDisplayed: 4.7µF  (hidden comment: C1608X6S1C475K080AC)
CAP, CERM, 4.7 µF, 16 V,+/- 10%, X6S, 0603; Manufacturer: TDK; Polarized: N; CompType: Capacitor; Value: 4.7uF; U/M: EA; Cap_F: 0.0000047; Tolerance_%: 10; ESR_ohm: 0.003728; Value1: 0.003728 ohm; VDC_V: 16; Value2: 16V; IRMS_A: 2.69359; TaMin_C: -55; TaMax_C: 105; Cap_Case: 0603; SizeArea_mm2: 1.28; SizeAreaWB_mm2: 4.68; SizeX_mm: 1.6; SizeY_mm: 0.8; SizeZ_mm: 1; AEC Category: Q200
signal-integrity model Cap
simulation model Cap
footprint 0603
footprint 0603M
footprint 0603L
footprint 0603_HV
footprint 0603S
pins: 1, 2

## C1608X6S1H105K080AC
designator C?  ValueDisplayed: 1µF  (hidden comment: C1608X6S1H105K080AC)
CAP, CERM, 1 µF, 50 V,+/- 10%, X6S, 0603; Manufacturer: TDK; Polarized: N; CompType: Capacitor; Value: 1uF; U/M: EA; Cap_F: 0.000001; Tolerance_%: 10; ESR_ohm: 0.005522; Value1: 0.005522 ohm; VDC_V: 50; Value2: 50V; IRMS_A: 2.21617; TaMin_C: -55; TaMax_C: 105; Cap_Case: 0603; SizeArea_mm2: 1.28; SizeAreaWB_mm2: 4.68; SizeX_mm: 1.6; SizeY_mm: 0.8; SizeZ_mm: 1; AEC Category: Q200
signal-integrity model Cap
simulation model Cap
footprint 0603
footprint 0603M
footprint 0603L
footprint 0603_HV
footprint 0603S
pins: 1, 2

## C1608X6S1H154K080AB
designator C?  ValueDisplayed: 0.15µF  (hidden comment: C1608X6S1H154K080AB)
CAP, CERM, 0.15 µF, 50 V,+/- 10%, X6S, 0603; Manufacturer: TDK; Polarized: N; CompType: Capacitor; Value: 0.15uF; U/M: EA; Cap_F: 0.00000015; Tolerance_%: 10; ESR_ohm: 0.028863; Value1: 0.028863 ohm; VDC_V: 50; Value2: 50V; IRMS_A: 0.978809; TaMin_C: -55; TaMax_C: 105; Cap_Case: 0603; SizeArea_mm2: 1.28; SizeAreaWB_mm2: 4.68; SizeX_mm: 1.6; SizeY_mm: 0.8; SizeZ_mm: 1; AEC Category: Q200
signal-integrity model Cap
simulation model Cap
footprint 0603
footprint 0603M
footprint 0603L
footprint 0603_HV
footprint 0603S
pins: 1, 2

## C1608X6S1H224K080AB
designator C?  ValueDisplayed: 0.22µF  (hidden comment: C1608X6S1H224K080AB)
CAP, CERM, 0.22 µF, 50 V,+/- 10%, X6S, 0603; Manufacturer: TDK; Polarized: N; CompType: Capacitor; Value: 0.22uF; U/M: EA; Cap_F: 0.00000022; Tolerance_%: 10; ESR_ohm: 0.021699; Value1: 0.021699 ohm; VDC_V: 50; Value2: 50V; IRMS_A: 1.12496; TaMin_C: -55; TaMax_C: 105; Cap_Case: 0603; SizeArea_mm2: 1.28; SizeAreaWB_mm2: 4.68; SizeX_mm: 1.6; SizeY_mm: 0.8; SizeZ_mm: 1; AEC Category: Q200
signal-integrity model Cap
simulation model Cap
footprint 0603
footprint 0603M
footprint 0603L
footprint 0603_HV
footprint 0603S
pins: 1, 2

## C1608X6S1H334K080AB
designator C?  ValueDisplayed: 0.33µF  (hidden comment: C1608X6S1H334K080AB)
CAP, CERM, 0.33 µF, 50 V,+/- 10%, X6S, 0603; Manufacturer: TDK; Polarized: N; CompType: Capacitor; Value: 0.33uF; U/M: EA; Cap_F: 0.00000033; Tolerance_%: 10; ESR_ohm: 0.016574; Value1: 0.016574 ohm; VDC_V: 50; Value2: 50V; IRMS_A: 1.28367; TaMin_C: -55; TaMax_C: 105; Cap_Case: 0603; SizeArea_mm2: 1.28; SizeAreaWB_mm2: 4.68; SizeX_mm: 1.6; SizeY_mm: 0.8; SizeZ_mm: 1; AEC Category: Q200
signal-integrity model Cap
simulation model Cap
footprint 0603
footprint 0603M
footprint 0603L
footprint 0603_HV
footprint 0603S
pins: 1, 2

## C1608X6S1H474K080AB
designator C?  ValueDisplayed: 0.47µF  (hidden comment: C1608X6S1H474K080AB)
CAP, CERM, 0.47 µF, 50 V,+/- 10%, X6S, 0603; Manufacturer: TDK; Polarized: N; CompType: Capacitor; Value: 0.47uF; U/M: EA; Cap_F: 0.00000047; Tolerance_%: 10; ESR_ohm: 0.010974; Value1: 0.010974 ohm; VDC_V: 50; Value2: 50V; IRMS_A: 1.57483; TaMin_C: -55; TaMax_C: 105; Cap_Case: 0603; SizeArea_mm2: 1.28; SizeAreaWB_mm2: 4.68; SizeX_mm: 1.6; SizeY_mm: 0.8; SizeZ_mm: 1; AEC Category: Q200
signal-integrity model Cap
simulation model Cap
footprint 0603
footprint 0603M
footprint 0603L
footprint 0603_HV
footprint 0603S
pins: 1, 2

## C1608X6S1H684K080AC
designator C?  ValueDisplayed: 0.68µF  (hidden comment: C1608X6S1H684K080AC)
CAP, CERM, 0.68 µF, 50 V,+/- 10%, X6S, 0603; Manufacturer: TDK; Polarized: N; CompType: Capacitor; Value: 0.68uF; U/M: EA; Cap_F: 0.00000068; Tolerance_%: 10; ESR_ohm: 0.007125; Value1: 0.007125 ohm; VDC_V: 50; Value2: 50V; IRMS_A: 1.9522; TaMin_C: -55; TaMax_C: 105; Cap_Case: 0603; SizeArea_mm2: 1.28; SizeAreaWB_mm2: 4.68; SizeX_mm: 1.6; SizeY_mm: 0.8; SizeZ_mm: 1; AEC Category: Q200
signal-integrity model Cap
simulation model Cap
footprint 0603
footprint 0603M
footprint 0603L
footprint 0603_HV
footprint 0603S
pins: 1, 2

## C1608X7R1A155K080AC
designator C?  ValueDisplayed: 1.5µF  (hidden comment: C1608X7R1A155K080AC)
CAP, CERM, 1.5 µF, 10 V,+/- 10%, X7R, 0603; Manufacturer: TDK; Polarized: N; CompType: Capacitor; Value: 1.5uF; U/M: EA; Cap_F: 0.0000015; Tolerance_%: 10; ESR_ohm: 0.004327; Value1: 0.004327 ohm; Value2: 10V; IRMS_A: 2.50174; TaMin_C: -55; TaMax_C: 125; Cap_Case: 0603; SizeArea_mm2: 1.28; SizeAreaWB_mm2: 4.68; SizeX_mm: 1.6; SizeY_mm: 0.8; SizeZ_mm: 1; AEC Category: Q200
signal-integrity model Cap
simulation model Cap
footprint 0603
footprint 0603M
footprint 0603L
footprint 0603_HV
footprint 0603S
pins: 1, 2

## C1608X7R1A225K080AC
designator C?  ValueDisplayed: 2.2µF  (hidden comment: C1608X7R1A225K080AC)
CAP, CERM, 2.2 µF, 10 V,+/- 10%, X7R, 0603; Manufacturer: TDK; Polarized: N; CompType: Capacitor; Value: 2.2uF; U/M: EA; Cap_F: 0.0000022; Tolerance_%: 10; ESR_ohm: 0.004058; Value1: 0.004058 ohm; Value2: 10V; IRMS_A: 2.58266; TaMin_C: -55; TaMax_C: 125; Cap_Case: 0603; SizeArea_mm2: 1.28; SizeAreaWB_mm2: 4.68; SizeX_mm: 1.6; SizeY_mm: 0.8; SizeZ_mm: 1; AEC Category: Q200; Green_Lifecycle: Active; Green_REACh: Passed
signal-integrity model Cap
simulation model Cap
footprint 0603
footprint 0603M
footprint 0603L
footprint 0603_HV
footprint 0603S
pins: 1, 2

## C1608X7R1C105K080AC
designator C?  ValueDisplayed: 1µF  (hidden comment: C1608X7R1C105K080AC)
CAP, CERM, 1 µF, 16 V,+/- 10%, X7R, 0603; Manufacturer: TDK; Polarized: N; CompType: Capacitor; Value: 1uF; U/M: EA; Cap_F: 0.000001; Tolerance_%: 10; ESR_ohm: 0.0057; Value1: 0.0057 ohm; VDC_V: 16; Value2: 16V; TaMin_C: -55; TaMax_C: 125; Cap_Case: 0603; SizeArea_mm2: 1.28; SizeAreaWB_mm2: 4.68; SizeX_mm: 1.6; SizeY_mm: 0.8; SizeZ_mm: 1; AEC Category: Q200; Green_Lifecycle: Active; Green_REACh: Passed
signal-integrity model Cap
simulation model Cap
footprint 0603
footprint 0603M
footprint 0603L
footprint 0603_HV
footprint 0603S
pins: 1, 2

## C1608X7R1C224K080AC
designator C?  ValueDisplayed: 0.22µF  (hidden comment: C1608X7R1C224K080AC)
CAP, CERM, 0.22 µF, 16 V,+/- 10%, X7R, 0603; Manufacturer: TDK; Polarized: N; CompType: Capacitor; Value: 0.22uF; U/M: EA; Cap_F: 0.00000022; Tolerance_%: 10; ESR_ohm: 0.0125; Value1: 0.0125 ohm; VDC_V: 16; Value2: 16V; TaMin_C: -55; TaMax_C: 125; Cap_Case: 0603; SizeArea_mm2: 1.28; SizeAreaWB_mm2: 4.68; SizeX_mm: 1.6; SizeY_mm: 0.8; SizeZ_mm: 1; AEC Category: Q200; Green_Lifecycle: NRND; Green_REACh: Passed
signal-integrity model Cap
simulation model Cap
footprint 0603
footprint 0603M
footprint 0603L
footprint 0603_HV
footprint 0603S
pins: 1, 2

## C1608X7R1E104K080AA
designator C?  ValueDisplayed: 0.1µF  (hidden comment: C1608X7R1E104K080AA)
CAP, CERM, 0.1 µF, 25 V,+/- 10%, X7R, 0603; Manufacturer: TDK; Polarized: N; CompType: Capacitor; Value: 0.1uF; U/M: EA; Cap_F: 0.0000001; Tolerance_%: 10; VDC_V: 25; Value2: 25V; TaMin_C: -55; TaMax_C: 125; Cap_Case: 0603; SizeArea_mm2: 1.28; SizeAreaWB_mm2: 4.68; SizeX_mm: 1.6; SizeY_mm: 0.8; SizeZ_mm: 1; AEC Category: Q200; Green_Lifecycle: NRND; Green_REACh: Passed
signal-integrity model Cap
simulation model Cap
footprint 0603
footprint 0603M
footprint 0603L
footprint 0603_HV
footprint 0603S
pins: 1, 2

## C1608X7R1E105K080AB
designator C?  ValueDisplayed: 1µF  (hidden comment: C1608X7R1E105K080AB)
CAP, CERM, 1 µF, 25 V,+/- 10%, X7R, 0603; Manufacturer: TDK; Polarized: N; CompType: Capacitor; Value: 1uF; U/M: EA; Cap_F: 0.000001; Tolerance_%: 10; VDC_V: 25; Value2: 25V; TaMin_C: -55; TaMax_C: 125; Cap_Case: 0603; SizeArea_mm2: 1.28; SizeAreaWB_mm2: 4.68; SizeX_mm: 1.6; SizeY_mm: 0.8; SizeZ_mm: 1; AEC Category: Q200; Green_Lifecycle: Active; Green_REACh: Passed
signal-integrity model Cap
simulation model Cap
footprint 0603
footprint 0603M
footprint 0603L
footprint 0603_HV
footprint 0603S
pins: 1, 2

## C1608X7R1E154K080AA
designator C?  ValueDisplayed: 0.15µF  (hidden comment: C1608X7R1E154K080AA)
CAP, CERM, 0.15 µF, 25 V,+/- 10%, X7R, 0603; Manufacturer: TDK; Polarized: N; CompType: Capacitor; Value: 0.15uF; U/M: EA; Cap_F: 0.00000015; Tolerance_%: 10; VDC_V: 25; Value2: 25V; TaMin_C: -55; TaMax_C: 125; Cap_Case: 0603; SizeArea_mm2: 1.28; SizeAreaWB_mm2: 4.68; SizeX_mm: 1.6; SizeY_mm: 0.8; SizeZ_mm: 1; AEC Category: Q200; Green_Lifecycle: Active; Green_REACh: Passed
signal-integrity model Cap
simulation model Cap
footprint 0603
footprint 0603M
footprint 0603L
footprint 0603_HV
footprint 0603S
pins: 1, 2

## C1608X7R1E224K080AC
designator C?  ValueDisplayed: 0.22µF  (hidden comment: C1608X7R1E224K080AC)
CAP, CERM, 0.22 µF, 25 V,+/- 10%, X7R, 0603; Manufacturer: TDK; Polarized: N; CompType: Capacitor; Value: 0.22uF; U/M: EA; Cap_F: 0.00000022; Tolerance_%: 10; VDC_V: 25; Value2: 25V; TaMin_C: -55; TaMax_C: 125; Cap_Case: 0603; SizeArea_mm2: 1.28; SizeAreaWB_mm2: 4.68; SizeX_mm: 1.6; SizeY_mm: 0.8; SizeZ_mm: 1; AEC Category: Q200
signal-integrity model Cap
simulation model Cap
footprint 0603
footprint 0603M
footprint 0603L
footprint 0603_HV
footprint 0603S
pins: 1, 2

## C1608X7R1H103K080AA
designator C?  ValueDisplayed: 0.01µF  (hidden comment: C1608X7R1H103K080AA)
CAP, CERM, 0.01 µF, 50 V,+/- 10%, X7R, 0603; Manufacturer: TDK; Polarized: N; CompType: Capacitor; Value: 0.01uF; U/M: EA; Cap_F: 0.00000001; Tolerance_%: 10; ESR_ohm: 0.0539; Value1: 0.0539 ohm; VDC_V: 50; Value2: 50V; TaMin_C: -55; TaMax_C: 125; Cap_Case: 0603; SizeArea_mm2: 1.28; SizeAreaWB_mm2: 4.68; SizeX_mm: 1.6; SizeY_mm: 0.8; SizeZ_mm: 1; AEC Category: Q200; Green_Lifecycle: NRND; Green_REACh: Passed
signal-integrity model Cap
simulation model Cap
footprint 0603
footprint 0603M
footprint 0603L
footprint 0603_HV
footprint 0603S
pins: 1, 2

## C1608X7R1H104K080AA
designator C?  ValueDisplayed: 0.1µF  (hidden comment: C1608X7R1H104K080AA)
CAP, CERM, 0.1 µF, 50 V,+/- 10%, X7R, 0603; Manufacturer: TDK; Polarized: N; CompType: Capacitor; Value: 0.1uF; U/M: EA; Cap_F: 0.0000001; Tolerance_%: 10; ESR_ohm: 0.0296; Value1: 0.0296 ohm; VDC_V: 50; Value2: 50V; IRMS_A: 0.97199; TaMin_C: -55; TaMax_C: 125; Cap_Case: 0603; SizeArea_mm2: 1.28; SizeAreaWB_mm2: 4.68; SizeX_mm: 1.6; SizeY_mm: 0.8; SizeZ_mm: 1; AEC Category: Q200; Green_Lifecycle: NRND; Green_REACh: Passed
signal-integrity model Cap
simulation model Cap
footprint 0603
footprint 0603M
footprint 0603L
footprint 0603_HV
footprint 0603S
pins: 1, 2

## C1608X7R1H153K080AA
designator C?  ValueDisplayed: 0.015µF  (hidden comment: C1608X7R1H153K080AA)
CAP, CERM, 0.015 µF, 50 V,+/- 10%, X7R, AEC-Q200 Grade 1, 0603; Manufacturer: TDK; Polarized: N; CompType: Capacitor; Value: 0.015uF; U/M: EA; Cap_F: 0.000000015; Tolerance_%: 10; VDC_V: 50; Value2: 50V; TaMin_C: -55; TaMax_C: 125; Cap_Case: 0603; SizeArea_mm2: 1.28; SizeAreaWB_mm2: 4.68; SizeX_mm: 1.6; SizeY_mm: 0.8; SizeZ_mm: 1; AEC Category: Q200; AEC Qualified: Y; Green_Lifecycle: Not Set; Green_REACh: Incomplete
signal-integrity model Cap
simulation model Cap
footprint 0603
footprint 0603M
footprint 0603L
footprint 0603_HV
footprint 0603S
pins: 1, 2

## C1608X7R1H154K080AB
designator C?  ValueDisplayed: 0.15µF  (hidden comment: C1608X7R1H154K080AB)
CAP, CERM, 0.15 µF, 50 V,+/- 10%, X7R, 0603; Manufacturer: TDK; Polarized: N; CompType: Capacitor; Value: 0.15uF; U/M: EA; Cap_F: 0.00000015; Tolerance_%: 10; ESR_ohm: 0.028863; Value1: 0.028863 ohm; VDC_V: 50; Value2: 50V; IRMS_A: 0.978809; TaMin_C: -55; TaMax_C: 125; Cap_Case: 0603; SizeArea_mm2: 1.28; SizeAreaWB_mm2: 4.68; SizeX_mm: 1.6; SizeY_mm: 0.8; SizeZ_mm: 1; AEC Category: Q200
signal-integrity model Cap
simulation model Cap
footprint 0603
footprint 0603M
footprint 0603L
footprint 0603_HV
footprint 0603S
pins: 1, 2

## C1608X7R1H224K080AB
designator C?  ValueDisplayed: 0.22µF  (hidden comment: C1608X7R1H224K080AB)
CAP, CERM, 0.22 µF, 50 V,+/- 10%, X7R, 0603; Manufacturer: TDK; Polarized: N; CompType: Capacitor; Value: 0.22uF; U/M: EA; Cap_F: 0.00000022; Tolerance_%: 10; ESR_ohm: 0.021699; Value1: 0.021699 ohm; VDC_V: 50; Value2: 50V; IRMS_A: 1.12496; TaMin_C: -55; TaMax_C: 125; Cap_Case: 0603; SizeArea_mm2: 1.28; SizeAreaWB_mm2: 4.68; SizeX_mm: 1.6; SizeY_mm: 0.8; SizeZ_mm: 1; AEC Category: Q200; Green_Lifecycle: Active; Green_REACh: Passed
signal-integrity model Cap
simulation model Cap
footprint 0603
footprint 0603M
footprint 0603L
footprint 0603_HV
footprint 0603S
pins: 1, 2

## C1608X7R1H334K080AC
designator C?  ValueDisplayed: 0.33µF  (hidden comment: C1608X7R1H334K080AC)
CAP, CERM, 0.33 µF, 50 V,+/- 10%, X7R, 0603; Manufacturer: TDK; Polarized: N; CompType: Capacitor; Value: 0.33uF; U/M: EA; Cap_F: 0.00000033; Tolerance_%: 10; ESR_ohm: 0.016574; Value1: 0.016574 ohm; VDC_V: 50; Value2: 50V; IRMS_A: 1.28367; TaMin_C: -55; TaMax_C: 125; Cap_Case: 0603; SizeArea_mm2: 1.28; SizeAreaWB_mm2: 4.68; SizeX_mm: 1.6; SizeY_mm: 0.8; SizeZ_mm: 1; AEC Category: Q200
signal-integrity model Cap
simulation model Cap
footprint 0603
footprint 0603M
footprint 0603L
footprint 0603_HV
footprint 0603S
pins: 1, 2

## C1608X7R1H473K080AA
designator C?  ValueDisplayed: 0.047µF  (hidden comment: C1608X7R1H473K080AA)
CAP, CERM, 0.047 µF, 50 V,+/- 10%, X7R, 0603; Manufacturer: TDK; Polarized: N; CompType: Capacitor; Value: 0.047uF; U/M: EA; Cap_F: 0.000000047; Tolerance_%: 10; ESR_ohm: 0.049007; Value1: 0.049007 ohm; VDC_V: 50; Value2: 50V; IRMS_A: 0.767528; TaMin_C: -55; TaMax_C: 125; Cap_Case: 0603; SizeArea_mm2: 1.28; SizeAreaWB_mm2: 4.68; SizeX_mm: 1.6; SizeY_mm: 0.8; SizeZ_mm: 1; AEC Category: Q200; Green_Lifecycle: NRND; Green_REACh: Passed
signal-integrity model Cap
simulation model Cap
footprint 0603
footprint 0603M
footprint 0603L
footprint 0603_HV
footprint 0603S
pins: 1, 2

## C1608X7R1H474K080AC
designator C?  ValueDisplayed: 0.47µF  (hidden comment: C1608X7R1H474K080AC)
CAP, CERM, 0.47 µF, 50 V,+/- 10%, X7R, 0603; Manufacturer: TDK; Polarized: N; CompType: Capacitor; Value: 0.47uF; U/M: EA; Cap_F: 0.00000047; Tolerance_%: 10; ESR_ohm: 0.010974; Value1: 0.010974 ohm; VDC_V: 50; Value2: 50V; IRMS_A: 1.57483; TaMin_C: -55; TaMax_C: 125; Cap_Case: 0603; SizeArea_mm2: 1.28; SizeAreaWB_mm2: 4.68; SizeX_mm: 1.6; SizeY_mm: 0.8; SizeZ_mm: 1; AEC Category: Q200; Green_Lifecycle: Active; Green_REACh: Passed
signal-integrity model Cap
simulation model Cap
footprint 0603
footprint 0603M
footprint 0603L
footprint 0603_HV
footprint 0603S
pins: 1, 2

## C1608X7R1H683K080AA
designator C?  ValueDisplayed: 0.068µF  (hidden comment: C1608X7R1H683K080AA)
CAP, CERM, 0.068 µF, 50 V,+/- 10%, X7R, 0603; Manufacturer: TDK; Polarized: N; CompType: Capacitor; Value: 0.068uF; U/M: EA; Cap_F: 0.000000068; Tolerance_%: 10; ESR_ohm: 0.035979; Value1: 0.035979 ohm; VDC_V: 50; Value2: 50V; IRMS_A: 0.886483; TaMin_C: -55; TaMax_C: 125; Cap_Case: 0603; SizeArea_mm2: 1.28; SizeAreaWB_mm2: 4.68; SizeX_mm: 1.6; SizeY_mm: 0.8; SizeZ_mm: 1; AEC Category: Q200
signal-integrity model Cap
simulation model Cap
footprint 0603
footprint 0603M
footprint 0603L
footprint 0603_HV
footprint 0603S
pins: 1, 2

## C1608X7R1V105K080AC
designator C?  ValueDisplayed: 1µF  (hidden comment: C1608X7R1V105K080AC)
CAP, CERM, 1 µF, 35 V,+/- 10%, X7R, 0603; Manufacturer: TDK; Polarized: N; CompType: Capacitor; Value: 1uF; U/M: EA; Cap_F: 0.000001; Tolerance_%: 10; VDC_V: 35; Value2: 35V; TaMin_C: -55; TaMax_C: 125; Cap_Case: 0603; SizeArea_mm2: 1.28; SizeAreaWB_mm2: 4.68; SizeX_mm: 1.6; SizeY_mm: 0.8; SizeZ_mm: 1; AEC Category: Q200; Green_Lifecycle: Active; Green_REACh: Passed
signal-integrity model Cap
simulation model Cap
footprint 0603
footprint 0603M
footprint 0603L
footprint 0603_HV
footprint 0603S
pins: 1, 2

## C1608X7R2A102K080AA
designator C?  ValueDisplayed: 1000pF  (hidden comment: C1608X7R2A102K080AA)
CAP, CERM, 1000 pF, 100 V,+/- 10%, X7R, 0603; Manufacturer: TDK; Polarized: N; CompType: Capacitor; Value: 1000pF; U/M: EA; Cap_F: 0.000000001; Tolerance_%: 10; VDC_V: 100; Value2: 100V; TaMin_C: -55; TaMax_C: 125; Cap_Case: 0603; SizeArea_mm2: 1.28; SizeAreaWB_mm2: 4.68; SizeX_mm: 1.6; SizeY_mm: 0.8; SizeZ_mm: 1; AEC Category: Q200; Green_Lifecycle: Active; Green_REACh: Passed
signal-integrity model Cap
simulation model Cap
footprint 0603
footprint 0603M
footprint 0603L
footprint 0603_HV
footprint 0603S
pins: 1, 2

## C1608X7R2A223K080AA
designator C?  ValueDisplayed: 0.022µF  (hidden comment: C1608X7R2A223K080AA)
CAP, CERM, 0.022 µF, 100 V,+/- 10%, X7R, 0603; Manufacturer: TDK; Polarized: N; CompType: Capacitor; Value: 0.022uF; U/M: EA; Cap_F: 0.000000022; Tolerance_%: 10; ESR_ohm: 0.037; Value1: 0.037 ohm; VDC_V: 100; Value2: 100V; TaMin_C: -55; TaMax_C: 125; Cap_Case: 0603; SizeArea_mm2: 1.28; SizeAreaWB_mm2: 4.68; SizeX_mm: 1.6; SizeY_mm: 0.8; SizeZ_mm: 1; AEC Category: Q200; Green_Lifecycle: Active; Green_REACh: Passed
signal-integrity model Cap
simulation model Cap
footprint 0603
footprint 0603M
footprint 0603L
footprint 0603_HV
footprint 0603S
pins: 1, 2

## C1608X7S0J106M080AC
designator C?  ValueDisplayed: 10µF  (hidden comment: C1608X7S0J106M080AC)
CAP, CERM, 10 µF, 6.3 V,+/- 20%, X7S, 0603; Manufacturer: TDK; Polarized: N; CompType: Capacitor; Value: 10uF; U/M: EA; Cap_F: 0.00001; Tolerance_%: 20; ESR_ohm: 0.004639; Value1: 0.004639 ohm; VDC_V: 6.3; Value2: 6.3V; IRMS_A: 2.41407; TaMin_C: -55; TaMax_C: 125; Cap_Case: 0603; SizeArea_mm2: 1.28; SizeAreaWB_mm2: 4.68; SizeX_mm: 1.6; SizeY_mm: 0.8; SizeZ_mm: 1; AEC Category: Q200
signal-integrity model Cap
simulation model Cap
footprint 0603
footprint 0603M
footprint 0603L
footprint 0603_HV
footprint 0603S
pins: 1, 2

## C1608X7S0J685K080AC
designator C?  ValueDisplayed: 6.8µF  (hidden comment: C1608X7S0J685K080AC)
CAP, CERM, 6.8 µF, 6.3 V,+/- 10%, X7S, 0603; Manufacturer: TDK; Polarized: N; CompType: Capacitor; Value: 6.8uF; U/M: EA; Cap_F: 0.0000068; Tolerance_%: 10; ESR_ohm: 0.004211; Value1: 0.004211 ohm; VDC_V: 6.3; Value2: 6.3V; IRMS_A: 2.534067; TaMin_C: -55; TaMax_C: 125; Cap_Case: 0603; SizeArea_mm2: 1.28; SizeAreaWB_mm2: 4.68; SizeX_mm: 1.6; SizeY_mm: 0.8; SizeZ_mm: 1; AEC Category: Q200
signal-integrity model Cap
simulation model Cap
footprint 0603
footprint 0603M
footprint 0603L
footprint 0603_HV
footprint 0603S
pins: 1, 2

## C1608X7S1A335K080AC
designator C?  ValueDisplayed: 3.3µF  (hidden comment: C1608X7S1A335K080AC)
CAP, CERM, 3.3 µF, 10 V,+/- 10%, X7S, 0603; Manufacturer: TDK; Polarized: N; CompType: Capacitor; Value: 3.3uF; U/M: EA; Cap_F: 0.0000033; Tolerance_%: 10; ESR_ohm: 0.004796; Value1: 0.004796 ohm; Value2: 10V; IRMS_A: 2.37519; TaMin_C: -55; TaMax_C: 125; Cap_Case: 0603; SizeArea_mm2: 1.28; SizeAreaWB_mm2: 4.68; SizeX_mm: 1.6; SizeY_mm: 0.8; SizeZ_mm: 1; AEC Category: Q200; Green_Lifecycle: Active; Green_REACh: Passed
signal-integrity model Cap
simulation model Cap
footprint 0603
footprint 0603M
footprint 0603L
footprint 0603_HV
footprint 0603S
pins: 1, 2

## C1608X7S1A475K080AC
designator C?  ValueDisplayed: 4.7µF  (hidden comment: C1608X7S1A475K080AC)
CAP, CERM, 4.7 µF, 10 V,+/- 10%, X7S, 0603; Manufacturer: TDK; Polarized: N; CompType: Capacitor; Value: 4.7uF; U/M: EA; Cap_F: 0.0000047; Tolerance_%: 10; Value2: 10V; TaMin_C: -55; TaMax_C: 125; Cap_Case: 0603; SizeArea_mm2: 1.28; SizeAreaWB_mm2: 4.68; SizeX_mm: 1.6; SizeY_mm: 0.8; SizeZ_mm: 1; AEC Category: Q200; Green_Lifecycle: Active; Green_REACh: Passed
signal-integrity model Cap
simulation model Cap
footprint 0603
footprint 0603M
footprint 0603L
footprint 0603_HV
footprint 0603S
pins: 1, 2

## C1608X7S2A104K080AB
designator C?  ValueDisplayed: 0.1µF  (hidden comment: C1608X7S2A104K080AB)
CAP, CERM, 0.1 µF, 100 V,+/- 10%, X7S, 0603; Manufacturer: TDK; Polarized: N; CompType: Capacitor; Value: 0.1uF; U/M: EA; Cap_F: 0.0000001; Tolerance_%: 10; ESR_ohm: 0.04959; Value1: 0.04959 ohm; VDC_V: 100; Value2: 100V; IRMS_A: 0.751618; TaMin_C: -55; TaMax_C: 125; Cap_Case: 0603; SizeArea_mm2: 1.28; SizeAreaWB_mm2: 4.68; SizeX_mm: 1.6; SizeY_mm: 0.8; SizeZ_mm: 1; AEC Category: Q200
signal-integrity model Cap
simulation model Cap
footprint 0603
footprint 0603M
footprint 0603L
footprint 0603_HV
footprint 0603S
pins: 1, 2

## C1608X7S2A473K080AB
designator C?  ValueDisplayed: 0.047µF  (hidden comment: C1608X7S2A473K080AB)
CAP, CERM, 0.047 µF, 100 V,+/- 10%, X7S, 0603; Manufacturer: TDK; Polarized: N; CompType: Capacitor; Value: 0.047uF; U/M: EA; Cap_F: 0.000000047; Tolerance_%: 10; ESR_ohm: 0.089796; Value1: 0.089796 ohm; VDC_V: 100; Value2: 100V; IRMS_A: 0.567484; TaMin_C: -55; TaMax_C: 125; Cap_Case: 0603; SizeArea_mm2: 1.28; SizeAreaWB_mm2: 4.68; SizeX_mm: 1.6; SizeY_mm: 0.8; SizeZ_mm: 1; AEC Category: Q200
signal-integrity model Cap
simulation model Cap
footprint 0603
footprint 0603M
footprint 0603L
footprint 0603_HV
footprint 0603S
pins: 1, 2

## C1608X7S2A683K080AB
designator C?  ValueDisplayed: 0.068µF  (hidden comment: C1608X7S2A683K080AB)
CAP, CERM, 0.068 µF, 100 V,+/- 10%, X7S, 0603; Manufacturer: TDK; Polarized: N; CompType: Capacitor; Value: 0.068uF; U/M: EA; Cap_F: 0.000000068; Tolerance_%: 10; ESR_ohm: 0.074084; Value1: 0.074084 ohm; VDC_V: 100; Value2: 100V; IRMS_A: 0.61909; TaMin_C: -55; TaMax_C: 125; Cap_Case: 0603; SizeArea_mm2: 1.28; SizeAreaWB_mm2: 4.68; SizeX_mm: 1.6; SizeY_mm: 0.8; SizeZ_mm: 1; AEC Category: Q200
signal-integrity model Cap
simulation model Cap
footprint 0603
footprint 0603M
footprint 0603L
footprint 0603_HV
footprint 0603S
pins: 1, 2

## C1808C104KBRACTU
designator C?  ValueDisplayed: 0.1µF  (hidden comment: C1808C104KBRACTU)
CAP, CERM, 0.1 µF, 630 V,+/- 10%, X7R, 1808; Manufacturer: Kemet; Polarized: N; CompType: Capacitor; Value: 0.1uF; U/M: EA; Cap_F: 0.0000001; Tolerance_%: 10; VDC_V: 630; Value2: 630V; TaMin_C: -55; TaMax_C: 125; Cap_Case: 1808; SizeArea_mm2: 9; SizeAreaWB_mm2: 16.5; SizeX_mm: 4.5; SizeY_mm: 2; SizeZ_mm: 2.15; AEC Category: Q200; Green_Lifecycle: Not Set; Green_REACh: Incomplete
signal-integrity model Cap
simulation model Cap
footprint 1808_215
footprint 1808_215_M
footprint 1808_215_L
pins: 1, 2

## C1808C153KFRACTU
designator C?  ValueDisplayed: 0.015µF  (hidden comment: C1808C153KFRACTU)
CAP, CERM, 0.015 µF, 1500 V,+/- 10%, X7R, 1808; Manufacturer: Kemet; Polarized: N; CompType: Capacitor; Value: 0.015uF; U/M: EA; Cap_F: 0.000000015; Tolerance_%: 10; VDC_V: 1500; Value2: 1500V; TaMin_C: -55; TaMax_C: 125; Cap_Case: 1808; SizeArea_mm2: 9; SizeAreaWB_mm2: 16.5; SizeX_mm: 4.5; SizeY_mm: 2; SizeZ_mm: 2.15; AEC Category: Q200
signal-integrity model Cap
simulation model Cap
footprint 1808_215
footprint 1808_215_M
footprint 1808_215_L
pins: 1, 2

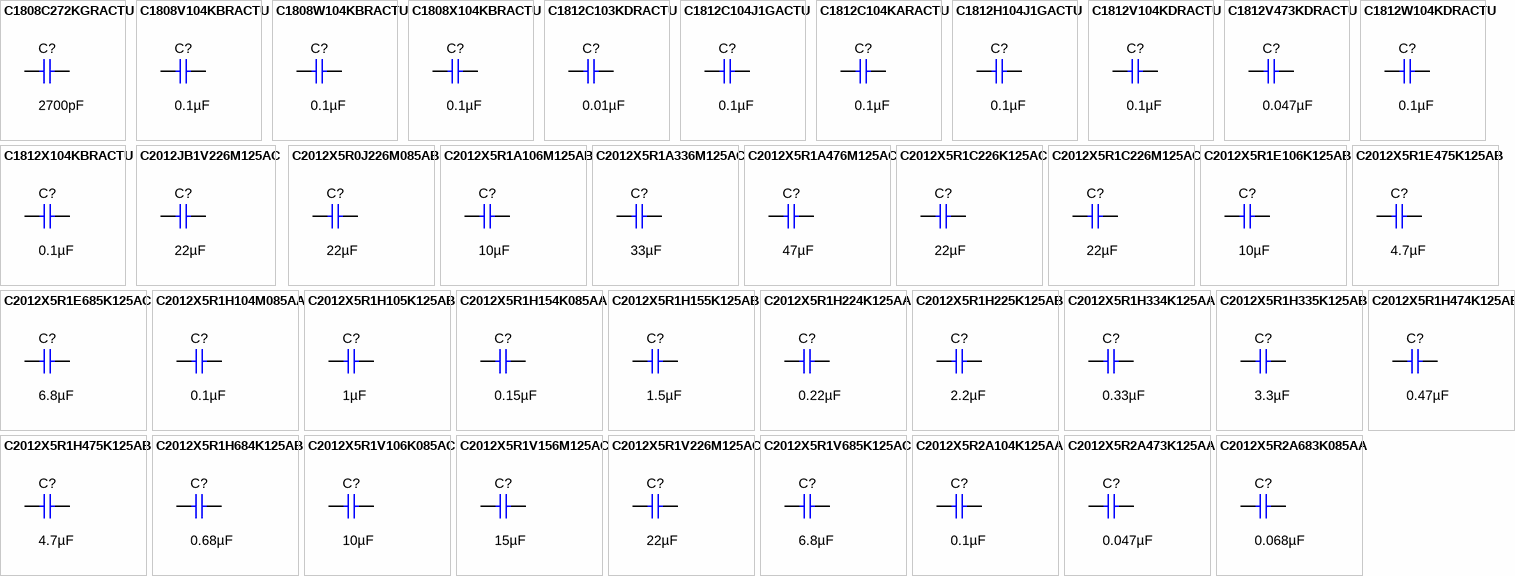
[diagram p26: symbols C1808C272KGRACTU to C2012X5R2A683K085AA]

## C1808C272KGRACTU
designator C?  ValueDisplayed: 2700pF  (hidden comment: C1808C272KGRACTU)
CAP, CERM, 2700 pF, 2000 V,+/- 10%, X7R, 1808; Manufacturer: Kemet; Polarized: N; CompType: Capacitor; Value: 2700pF; U/M: EA; Cap_F: 0.0000000027; Tolerance_%: 10; VDC_V: 2000; Value2: 2000V; TaMin_C: -55; TaMax_C: 125; Cap_Case: 1808; SizeArea_mm2: 9; SizeAreaWB_mm2: 16.5; SizeX_mm: 4.5; SizeY_mm: 2; SizeZ_mm: 2.03; AEC Category: Q200; Green_Lifecycle: Active; Green_REACh: Passed
signal-integrity model Cap
simulation model Cap
footprint 1808
footprint 1808_M
footprint 1808_L
pins: 1, 2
